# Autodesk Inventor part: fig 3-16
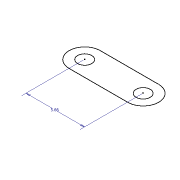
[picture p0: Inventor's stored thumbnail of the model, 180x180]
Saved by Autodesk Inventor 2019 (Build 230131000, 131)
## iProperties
Created: 2009-11
Part Number: fig 3-16
Document SubType Name: Modeling
Designer: Sham
Density: 1 g/cm^3
Material: Generic
Appearance: Default
Author: Sham
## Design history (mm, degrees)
sketch "Sketch1"
  geometry: L1 (4.59, -0.041)-(10.25, -0.041); L2 (4.59, -3.041)-(10.25, -3.041); C1 r 0.679 at (4.59, -1.541); C2 r 0.679 at (10.25, -1.541); A1 r 1.5 centre (4.59, -1.541) between (4.59, -0.041) and (4.59, -3.041); A2 r 1.5 centre (10.25, -1.541) between (10.25, -3.041) and (10.25, -0.041)
  constraints: 4 centre point, 4 end point, 4 point on circle, 2 coincident, 2 horizontal, 2 tangent, 1 equal radius
  dimensions: "d2" = 5.66 dimension on A1.centre A1 A2.centre A2 L1.start L1.end L1 L2.start L2.end L2 C1.centre C1 C2.centre C2; "d2" = 5.66 distance of A2.centre A1.centre
